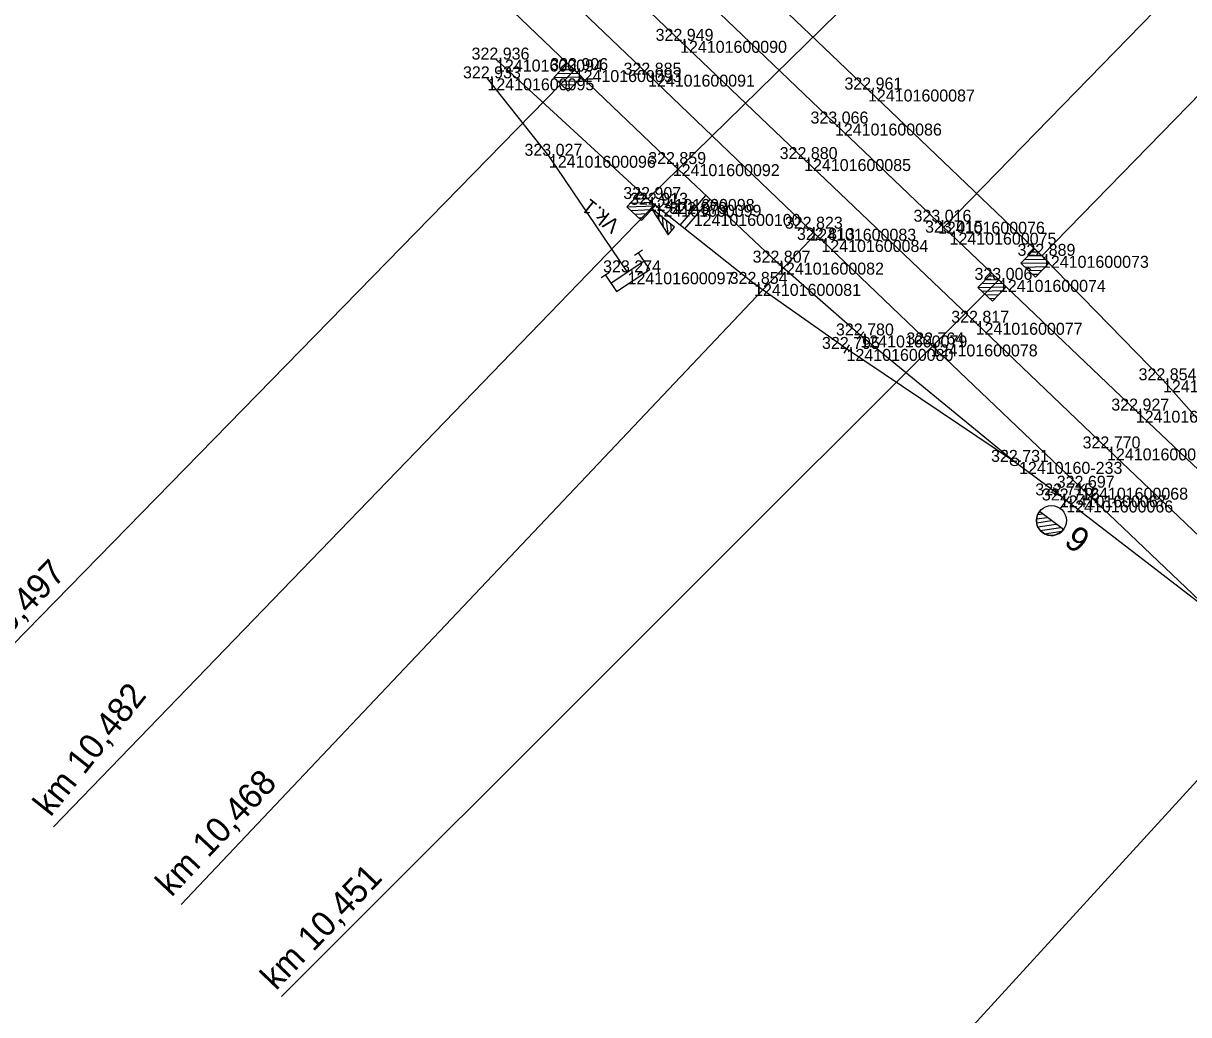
# Model space of a CAD drawing. Extents: x -616949 to -607976, y -1164436 to -1159224.
# Drawn here: x -616343.7 to -616226.9, y -1159749.3 to -1159650 of the extents above; entities that cross this region are included whole.
import ezdxf

# ---------------------------------------------------------------- set-up
doc = ezdxf.new("R2010")
doc.units = 0
for name, color, linetype in [('Vrstva 1', 7, 'Continuous'), ('Vrstva 15', 7, 'Continuous'), ('Vrstva 2', 7, 'Continuous'), ('Vrstva 3', 7, 'Continuous'), ('Vrstva 60', 7, 'Continuous'), ('Vrstva 61', 7, 'Continuous'), ('Vrstva 7', 7, 'Continuous')]:
    doc.layers.add(name, color=color, linetype=linetype)

msp = doc.modelspace()

# ---------------------------------------------------------------- linework, layer by layer
at = {"layer": 'Vrstva 1'}
msp.add_line((-616239.15, -1159697.79), (-616239.8, -1159697.28), dxfattribs=at)
for points in [[(-616239.15, -1159697.79), (-616239.8, -1159697.28), (-616244.33, -1159693.92), (-616259.78, -1159681.25), (-616268.13, -1159673.95), (-616278.58, -1159664.07), (-616288.41, -1159654.65), (-616299.9, -1159643.65), (-616322.63, -1159621.82), (-616340.65, -1159604.54), (-616363.83, -1159582.4), (-616382.82, -1159564.27), (-616397.71, -1159550.06), (-616401.16, -1159546.79), (-616418.73, -1159530.01), (-616439.27, -1159510.4), (-616452.37, -1159497.82), (-616461.42, -1159488.93), (-616469.22, -1159481.07), (-616478.64, -1159471.37), (-616490.77, -1159457.29), (-616495.92, -1159451.32), (-616496.45, -1159450.7)], [(-616196.14, -1159722.89), (-616196.73, -1159722.32), (-616202.46, -1159716.91), (-616215.79, -1159704.32), (-616232.19, -1159688.78), (-616245.9, -1159675.68), (-616250.85, -1159670.95), (-616252.01, -1159669.85), (-616262.33, -1159660.01), (-616274.66, -1159648.21), (-616291.39, -1159632.22), (-616312.18, -1159612.35), (-616313.6, -1159610.97), (-616321.94, -1159603.01), (-616323.38, -1159601.63), (-616330.7, -1159594.64), (-616332.15, -1159593.27), (-616353.46, -1159572.9), (-616354.89, -1159571.54), (-616372.69, -1159554.54)], [(-616218.05, -1159715.21), (-616218.66, -1159714.63), (-616224.36, -1159709.19), (-616237.66, -1159696.51), (-616252.73, -1159682.15), (-616263.69, -1159671.68), (-616264.9, -1159670.55), (-616281.06, -1159655.11), (-616297.26, -1159639.59), (-616319.41, -1159618.4), (-616337.57, -1159601.02), (-616360.84, -1159578.72), (-616379.28, -1159561.06)], [(-616196.14, -1159722.89), (-616196.73, -1159722.32), (-616202.46, -1159716.91), (-616214.6, -1159702.79), (-616223.47, -1159692.48), (-616229.46, -1159685.74), (-616241.59, -1159673.27), (-616259.02, -1159656.6), (-616271.36, -1159644.82), (-616287.75, -1159629.14), (-616308.99, -1159608.84), (-616310.74, -1159607.16), (-616318.53, -1159599.72), (-616320.21, -1159598.1), (-616327.35, -1159591.27), (-616329.08, -1159589.6), (-616351, -1159568.64)], [(-616166.13, -1159755.81), (-616181.17, -1159743.07), (-616197.09, -1159728.56), (-616212.13, -1159714.43), (-616235.07, -1159692.57), (-616248.23, -1159679.98), (-616265.42, -1159663.57), (-616277.85, -1159651.72), (-616294.35, -1159635.93), (-616315.47, -1159615.78), (-616316.9, -1159614.42), (-616325.14, -1159606.55), (-616326.55, -1159605.19), (-616333.88, -1159598.19), (-616335.34, -1159596.8), (-616356.93, -1159576.13)], [(-616239.15, -1159697.79), (-616239.8, -1159697.28), (-616244.33, -1159693.92), (-616261.17, -1159682.6), (-616270.43, -1159676.08), (-616280.41, -1159668.15), (-616281.09, -1159667.57), (-616296.29, -1159653.6)], [(-616283.11, -1159674.92), (-616290.99, -1159663.24), (-616297.15, -1159655.48)], [(-616218.05, -1159715.21), (-616218.66, -1159714.63), (-616224.36, -1159709.19), (-616239.15, -1159697.79)]]:
    msp.add_lwpolyline(points, dxfattribs=at)
at = {"layer": 'Vrstva 15'}
for p, q in [((-616281.6, -1159672.69), (-616282.43, -1159673.25)), ((-616281.45, -1159673.8), (-616284.77, -1159676.04)), ((-616284.91, -1159674.93), (-616285.74, -1159675.49))]:
    msp.add_line(p, q, dxfattribs=at)
msp.add_lwpolyline([(-616285.33, -1159675.21), (-616284.21, -1159676.86), (-616280.89, -1159674.63), (-616282.01, -1159672.97)], dxfattribs=at)
at = {"layer": 'Vrstva 2'}
for p, q in [((-616259.45, -1159680.87), (-616260.1, -1159681.62)), ((-616260.91, -1159682.18), (-616261.44, -1159683.03)), ((-616244.33, -1159693.92), (-616259.78, -1159681.25)), ((-616237.32, -1159696.15), (-616238.01, -1159696.87)), ((-616238.85, -1159697.4), (-616239.46, -1159698.19)), ((-616239.15, -1159697.79), (-616239.75, -1159698.59)), ((-616224.36, -1159709.19), (-616239.15, -1159697.79)), ((-616242.13, -1159699.63), (-616241.08, -1159699.48)), ((-616242.02, -1159699.21), (-616241.53, -1159699.14)), ((-616239.44, -1159700.69), (-616241.85, -1159698.9)), ((-616242.12, -1159700.04), (-616240.62, -1159699.81)), ((-616242, -1159700.42), (-616240.17, -1159700.15)), ((-616241.76, -1159700.79), (-616239.71, -1159700.49)), ((-616241.33, -1159701.13), (-616239.61, -1159700.88))]:
    msp.add_line(p, q, dxfattribs=at)
for points in [[(-616239.15, -1159697.79), (-616239.8, -1159697.28), (-616244.33, -1159693.92), (-616261.17, -1159682.6)], [(-616240.73, -1159696.91), (-616239.8, -1159697.28), (-616240.42, -1159696.5)], [(-616218.05, -1159715.21), (-616218.66, -1159714.63), (-616224.36, -1159709.19), (-616237.66, -1159696.51)]]:
    msp.add_lwpolyline(points, dxfattribs=at)
for centre, radius in [((-616244.33, -1159693.92), 0.4), ((-616240.64, -1159699.8), 1.5)]:
    msp.add_circle(centre, radius, dxfattribs=at)
msp.add_arc((-616240.64, -1159699.8), 1.5, 143.3947, 323.3947, dxfattribs=at)
at = {"layer": 'Vrstva 3'}
for p, q in [((-616281.09, -1159667.57), (-616232.24, -1159619.71)), ((-616251.43, -1159670.4), (-616213.9, -1159631.89)), ((-616241.59, -1159673.27), (-616205.79, -1159636.51)), ((-616288.41, -1159654.65), (-616349.59, -1159717.25)), ((-616290.51, -1159655.4), (-616287.68, -1159655.34)), ((-616290.15, -1159655.01), (-616288.07, -1159654.97)), ((-616289.78, -1159654.63), (-616288.45, -1159654.6)), ((-616289.41, -1159654.25), (-616288.83, -1159654.24)), ((-616290.13, -1159655.76), (-616288.05, -1159655.72)), ((-616289.75, -1159656.13), (-616288.42, -1159656.1)), ((-616289.36, -1159656.5), (-616288.79, -1159656.49)), ((-616280.41, -1159668.15), (-616340.62, -1159730.51)), ((-616282.82, -1159667.98), (-616280.74, -1159667.89)), ((-616282.46, -1159667.59), (-616281.13, -1159667.53)), ((-616282.1, -1159667.2), (-616281.52, -1159667.17)), ((-616283.18, -1159668.37), (-616280.35, -1159668.25)), ((-616282.79, -1159668.73), (-616280.71, -1159668.64)), ((-616282.4, -1159669.09), (-616281.07, -1159669.03)), ((-616280.47, -1159668.74), (-616280.43, -1159668.98)), ((-616280.05, -1159669.07), (-616279.99, -1159669.67)), ((-616282.01, -1159669.45), (-616281.43, -1159669.42)), ((-616279.64, -1159669.4), (-616279.54, -1159670.36)), ((-616279.23, -1159669.72), (-616279.09, -1159671.06)), ((-616278.82, -1159670.05), (-616278.75, -1159670.8)), ((-616263.69, -1159671.68), (-616264.9, -1159670.55)), ((-616250.85, -1159670.95), (-616252.01, -1159669.85)), ((-616264.29, -1159671.11), (-616327.85, -1159738.28)), ((-616242.59, -1159672.87), (-616242.02, -1159672.86)), ((-616243.69, -1159674.02), (-616240.87, -1159673.96)), ((-616243.33, -1159673.64), (-616241.25, -1159673.59)), ((-616242.96, -1159673.25), (-616241.63, -1159673.22)), ((-616243.31, -1159674.39), (-616241.23, -1159674.34)), ((-616242.93, -1159674.75), (-616241.6, -1159674.72)), ((-616242.54, -1159675.12), (-616241.97, -1159675.11)), ((-616245.9, -1159675.68), (-616317.78, -1159747.5)), ((-616248, -1159676.43), (-616245.18, -1159676.37)), ((-616247.64, -1159676.05), (-616245.56, -1159676)), ((-616247.27, -1159675.67), (-616245.94, -1159675.64)), ((-616246.9, -1159675.28), (-616246.33, -1159675.27)), ((-616247.62, -1159676.8), (-616245.54, -1159676.75)), ((-616247.24, -1159677.17), (-616245.91, -1159677.14)), ((-616246.85, -1159677.53), (-616246.27, -1159677.52)), ((-616217.13, -1159716.1), (-616262.93, -1159766.19))]:
    msp.add_line(p, q, dxfattribs=at)
for points in [[(-616289.13, -1159653.95), (-616287.68, -1159655.34), (-616289.07, -1159656.78), (-616290.51, -1159655.4)], [(-616281.82, -1159666.9), (-616280.35, -1159668.25), (-616281.7, -1159669.72), (-616283.18, -1159668.37)], [(-616280.72, -1159668.54), (-616279.03, -1159671.15), (-616278.41, -1159670.38)], [(-616242.31, -1159672.57), (-616240.87, -1159673.96), (-616242.25, -1159675.4), (-616243.69, -1159674.02)], [(-616246.62, -1159674.99), (-616245.18, -1159676.37), (-616246.56, -1159677.81), (-616248, -1159676.43)]]:
    msp.add_lwpolyline(points, close=True, dxfattribs=at)
at = {"layer": 'Vrstva 60'}
for p, q in [((-616277.85, -1159651.72), (-616277.85, -1159651.72)), ((-616296.29, -1159653.6), (-616296.29, -1159653.6)), ((-616288.41, -1159654.65), (-616288.41, -1159654.65)), ((-616281.06, -1159655.11), (-616281.06, -1159655.11)), ((-616297.15, -1159655.48), (-616297.15, -1159655.48)), ((-616259.02, -1159656.6), (-616259.02, -1159656.6)), ((-616262.33, -1159660.01), (-616262.33, -1159660.01)), ((-616290.99, -1159663.24), (-616290.99, -1159663.24)), ((-616278.58, -1159664.07), (-616278.58, -1159664.07)), ((-616265.42, -1159663.57), (-616265.42, -1159663.57)), ((-616281.09, -1159667.57), (-616281.09, -1159667.57)), ((-616280.41, -1159668.15), (-616280.41, -1159668.15)), ((-616276.48, -1159669.07), (-616276.48, -1159669.07)), ((-616264.9, -1159670.55), (-616264.9, -1159670.55)), ((-616252.01, -1159669.85), (-616252.01, -1159669.85)), ((-616263.69, -1159671.68), (-616263.69, -1159671.68)), ((-616250.85, -1159670.95), (-616250.85, -1159670.95)), ((-616268.13, -1159673.95), (-616268.13, -1159673.95)), ((-616241.59, -1159673.27), (-616241.59, -1159673.27)), ((-616283.11, -1159674.92), (-616283.11, -1159674.92)), ((-616270.43, -1159676.08), (-616270.43, -1159676.08)), ((-616245.9, -1159675.68), (-616245.9, -1159675.68)), ((-616248.23, -1159679.98), (-616248.23, -1159679.98)), ((-616259.78, -1159681.25), (-616259.78, -1159681.25)), ((-616252.73, -1159682.15), (-616252.73, -1159682.15)), ((-616261.17, -1159682.6), (-616261.17, -1159682.6)), ((-616229.46, -1159685.74), (-616229.46, -1159685.74)), ((-616232.19, -1159688.78), (-616232.19, -1159688.78)), ((-616235.07, -1159692.57), (-616235.07, -1159692.57)), ((-616244.33, -1159693.92), (-616244.33, -1159693.92)), ((-616239.8, -1159697.28), (-616239.8, -1159697.28)), ((-616237.66, -1159696.51), (-616237.66, -1159696.51)), ((-616239.15, -1159697.79), (-616239.15, -1159697.79))]:
    msp.add_line(p, q, dxfattribs=at)
at = {"layer": 'Vrstva 7'}
for p, q in [((-616277.84, -1159670.19), (-616275.26, -1159667.21)), ((-616277.37, -1159670.56), (-616274.83, -1159667.62)), ((-616276.48, -1159669.07), (-616276.48, -1159669.07))]:
    msp.add_line(p, q, dxfattribs=at)

# ---------------------------------------------------------------- texts
at = {"layer": 'Vrstva 2'}
msp.add_text('6', height=2.5, rotation=143.3947, dxfattribs=at).set_placement((-616236.53, -1159701.24))
at = {"layer": 'Vrstva 3'}
for s, height, rotation, p in [('Vk.1', 1.5, 141.5353, (-616283.76, -1159669.96)), ('km 10,497', 2.5, 46.1695, (-616350.07, -1159716.49)), ('km 10,482', 2.5, 51.5353, (-616340.92, -1159729.59)), ('km 10,468', 2.5, 46.7907, (-616328.81, -1159737.61)), ('km 10,451', 2.5, 46.2923, (-616318.33, -1159746.99))]:
    msp.add_text(s, height=height, rotation=rotation, dxfattribs=at).set_placement(p)
at = {"layer": 'Vrstva 60'}
for s, p in [('124101600090', (-616277.85, -1159652.92)), ('124101600094', (-616296.29, -1159654.8)), ('124101600093', (-616288.41, -1159655.85)), ('124101600091', (-616281.06, -1159656.31)), ('124101600095', (-616297.15, -1159656.68)), ('124101600087', (-616259.02, -1159657.8)), ('124101600086', (-616262.33, -1159661.21)), ('124101600096', (-616290.99, -1159664.44)), ('124101600085', (-616265.42, -1159664.77)), ('124101600092', (-616278.58, -1159665.28)), ('124101600098', (-616281.09, -1159668.77)), ('124101600099', (-616280.41, -1159669.35)), ('124101600100', (-616276.48, -1159670.27)), ('124101600083', (-616264.9, -1159671.75)), ('124101600076', (-616252.01, -1159671.05)), ('124101600084', (-616263.69, -1159672.88)), ('124101600075', (-616250.85, -1159672.15)), ('124101600082', (-616268.13, -1159675.15)), ('124101600073', (-616241.59, -1159674.47)), ('124101600097', (-616283.11, -1159676.12)), ('124101600081', (-616270.43, -1159677.28)), ('124101600074', (-616245.9, -1159676.88)), ('124101600077', (-616248.23, -1159681.18)), ('124101600079', (-616259.78, -1159682.45)), ('124101600078', (-616252.73, -1159683.35)), ('124101600080', (-616261.17, -1159683.8)), ('124101600071', (-616229.46, -1159686.94)), ('124101600070', (-616232.19, -1159689.99)), ('124101600069', (-616235.07, -1159693.77)), (' 12410160-233', (-616244.33, -1159695.12)), ('124101600067', (-616239.8, -1159698.48)), ('124101600068', (-616237.66, -1159697.71)), ('124101600066', (-616239.15, -1159698.99))]:
    msp.add_text(s, height=1.2, dxfattribs=at).set_placement(p)
at = {"layer": 'Vrstva 61'}
for s, p in [('322.949', (-616280.3, -1159651.72)), ('322.936', (-616298.74, -1159653.6)), ('322.906', (-616290.86, -1159654.65)), ('322.885', (-616283.51, -1159655.11)), ('322.933', (-616299.6, -1159655.48)), ('322.961', (-616261.38, -1159656.6)), ('323.066', (-616264.78, -1159660.01)), ('323.027', (-616293.44, -1159663.24)), ('322.880', (-616267.87, -1159663.57)), ('322.859', (-616281.04, -1159664.07)), ('322.907', (-616283.54, -1159667.57)), ('322.913', (-616282.86, -1159668.15)), ('322.873', (-616278.93, -1159669.07)), ('322.823', (-616267.35, -1159670.55)), ('323.016', (-616254.46, -1159669.85)), ('322.813', (-616266.14, -1159671.68)), ('323.015', (-616253.3, -1159670.95)), ('322.807', (-616270.58, -1159673.95)), ('322.889', (-616244.04, -1159673.27)), ('323.274', (-616285.56, -1159674.92)), ('322.854', (-616272.88, -1159676.08)), ('323.006', (-616248.35, -1159675.68)), ('322.817', (-616250.68, -1159679.98)), ('322.780', (-616262.23, -1159681.25)), ('322.764', (-616255.18, -1159682.15)), ('322.795', (-616263.63, -1159682.6)), ('322.854', (-616231.91, -1159685.74)), ('322.927', (-616234.64, -1159688.78)), ('322.770', (-616237.52, -1159692.57)), ('322.731', (-616246.69, -1159693.92)), ('322.715', (-616242.26, -1159697.28)), ('322.697', (-616240.11, -1159696.51)), ('322.716', (-616241.6, -1159697.79))]:
    msp.add_text(s, height=1.2, dxfattribs=at).set_placement(p)

doc.saveas('drawing.dxf')
